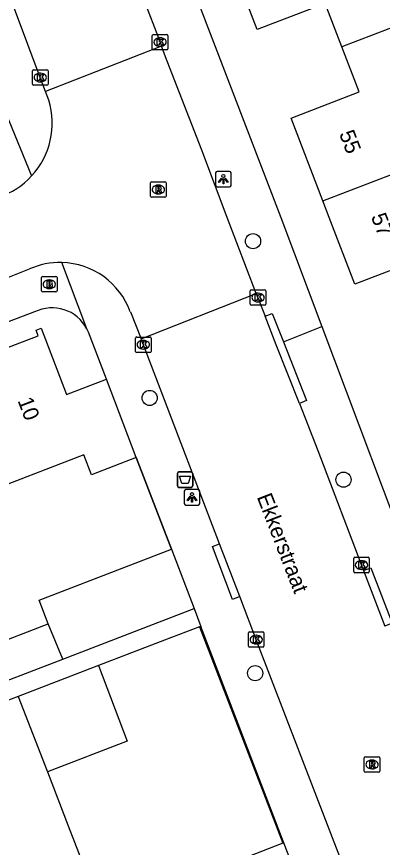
# Model space of a CAD drawing. Extents: x 159265 to 160143, y 383413 to 384319.
# Drawn here: x 159474 to 159497.6, y 383709.4 to 383763 of the extents above; entities that cross this region are included whole.
import ezdxf

# ---------------------------------------------------------------- set-up
doc = ezdxf.new("R2010")
doc.units = 0
for name, color, linetype in [('IMGEO_Afvalbak', 7, 'Continuous'), ('IMGEO_Boom', 7, 'Continuous'), ('IMGEO_Brandkraan', 7, 'Continuous'), ('IMGEO_Kolk', 7, 'Continuous'), ('IMGEO_Lichtpunt', 7, 'Continuous'), ('IMGEO_Muur', 7, 'Continuous'), ('IMGEO_Openbare_ruimte_label', 7, 'Continuous'), ('IMGEO_Pand', 7, 'Continuous'), ('IMGEO_Pand_nummerreeks', 7, 'Continuous'), ('IMGEO_Rijbaan_lokaal_gesloten', 7, 'Continuous'), ('IMGEO_Rijbaan_lokaal_open', 7, 'Continuous'), ('IMGEO_Rioolput', 7, 'Continuous'), ('IMGEO_Voetpad_open', 7, 'Continuous')]:
    doc.layers.add(name, color=color, linetype=linetype)

msp = doc.modelspace()

# ---------------------------------------------------------------- linework, layer by layer
at = {"layer": 'IMGEO_Afvalbak'}
for p, q in [((159484.442, 383733.589), (159485.232, 383733.589)), ((159485.232, 383733.589), (159484.442, 383733.589)), ((159484.342, 383732.689), (159484.342, 383733.489)), ((159484.342, 383733.489), (159484.342, 383732.689)), ((159485.332, 383733.489), (159485.332, 383732.689)), ((159485.332, 383732.689), (159485.332, 383733.489)), ((159485.232, 383732.589), (159484.442, 383732.589)), ((159484.442, 383732.589), (159485.232, 383732.589))]:
    msp.add_line(p, q, dxfattribs=at)
msp.add_lwpolyline([(159484.485, 383733.303), (159485.189, 383733.303), (159485.04, 383732.833), (159484.634, 383732.833), (159484.485, 383733.303)], dxfattribs=at)
for centre, start, end in [((159484.442, 383733.489), 90, 180), ((159484.442, 383733.489), 90, 180), ((159485.232, 383733.489), 0, 90), ((159485.232, 383733.489), 360, 90), ((159484.442, 383732.689), 180, 270), ((159484.442, 383732.689), 180, 270), ((159485.232, 383732.689), 270, 0), ((159485.232, 383732.689), 270, 0)]:
    msp.add_arc(centre, 0.1, start, end, dxfattribs=at)
at = {"layer": 'IMGEO_Boom'}
for centre in [(159489.216, 383748.468), (159482.553, 383738.358), (159495.05, 383733.087), (159489.356, 383720.608)]:
    msp.add_circle(centre, 0.489, dxfattribs=at)
at = {"layer": 'IMGEO_Brandkraan'}
for p, q in [((159475.58, 383745.266), (159475.58, 383746.118)), ((159475.655, 383746.192), (159476.507, 383746.192)), ((159476.068, 383745.972), (159476.093, 383745.972)), ((159476.581, 383746.118), (159476.581, 383745.266)), ((159476.091, 383745.412), (159476.066, 383745.412)), ((159476.507, 383745.192), (159475.655, 383745.192))]:
    msp.add_line(p, q, dxfattribs=at)
for points in [[(159475.58, 383745.266), (159475.58, 383746.118)], [(159475.655, 383746.192), (159476.507, 383746.192)], [(159475.928, 383745.892), (159475.928, 383745.492), (159476.141, 383745.492)], [(159476.159, 383745.892), (159475.928, 383745.892)], [(159476.581, 383746.118), (159476.581, 383745.266)], [(159476.107, 383745.811), (159476.053, 383745.811), (159476.053, 383745.735)], [(159476.053, 383745.735), (159476.106, 383745.735)], [(159476.115, 383745.659), (159476.053, 383745.659), (159476.053, 383745.578)], [(159476.053, 383745.578), (159476.115, 383745.578)], [(159476.507, 383745.192), (159475.655, 383745.192)]]:
    msp.add_lwpolyline(points, dxfattribs=at)
for centre, radius, start, end in [((159475.657, 383746.116), 0.0765, 91.552, 178.448), ((159475.657, 383746.116), 0.0765, 91.552, 178.448), ((159476.163, 383745.747), 0.145, 59.4692, 91.5367), ((159476.188, 383745.794), 0.0922, 285.5137, 58.1501), ((159476.505, 383746.116), 0.0765, 1.552, 88.448), ((159476.505, 383746.116), 0.0765, 1.552, 88.448), ((159476.108, 383745.773), 0.0379, 267.8285, 90.9355), ((159476.116, 383745.618), 0.0404, 269.8759, 90.5077), ((159476.147, 383745.743), 0.251, 268.6676, 293.5347), ((159476.193, 383745.602), 0.105, 301.3115, 78.989), ((159475.657, 383745.268), 0.0765, 181.552, 268.448), ((159475.657, 383745.268), 0.0765, 181.552, 268.448), ((159476.505, 383745.268), 0.0765, 271.552, 358.448), ((159476.505, 383745.268), 0.0765, 271.552, 358.448)]:
    msp.add_arc(centre, radius, start, end, dxfattribs=at)
for centre, major_axis, ratio, start_param, end_param in [((159476.067, 383745.692), (-0.387, 0.002), 0.722429, 4.712389, 7.853982), ((159476.092, 383745.692), (-0.39, 0.002), 0.717154, 1.570796, 4.712389)]:
    msp.add_ellipse(centre, major_axis=major_axis, ratio=ratio, start_param=start_param, end_param=end_param, dxfattribs=at)
at = {"layer": 'IMGEO_Kolk'}
for p, q in [((159482.723, 383760.881), (159482.723, 383761.733)), ((159482.798, 383761.807), (159483.65, 383761.807)), ((159483.211, 383761.587), (159483.236, 383761.587)), ((159483.724, 383761.733), (159483.724, 383760.881)), ((159483.234, 383761.027), (159483.209, 383761.027)), ((159483.65, 383760.807), (159482.798, 383760.807)), ((159474.998, 383758.597), (159474.998, 383759.449)), ((159475.073, 383759.523), (159475.925, 383759.523)), ((159475.486, 383759.303), (159475.511, 383759.303)), ((159475.999, 383759.449), (159475.999, 383758.597)), ((159475.509, 383758.743), (159475.484, 383758.743)), ((159475.925, 383758.523), (159475.073, 383758.523)), ((159489.113, 383745.335), (159489.965, 383745.335)), ((159489.038, 383744.409), (159489.038, 383745.261)), ((159489.526, 383745.115), (159489.551, 383745.115)), ((159490.039, 383745.261), (159490.039, 383744.409)), ((159489.965, 383744.335), (159489.113, 383744.335)), ((159489.549, 383744.555), (159489.524, 383744.555)), ((159481.642, 383741.362), (159481.642, 383742.214)), ((159481.717, 383742.288), (159482.569, 383742.288)), ((159482.13, 383742.068), (159482.155, 383742.068)), ((159482.643, 383742.214), (159482.643, 383741.362)), ((159482.569, 383741.288), (159481.717, 383741.288)), ((159482.153, 383741.508), (159482.128, 383741.508)), ((159495.713, 383727.155), (159495.713, 383728.007)), ((159495.788, 383728.081), (159496.64, 383728.081)), ((159496.201, 383727.861), (159496.226, 383727.861)), ((159496.714, 383728.007), (159496.714, 383727.155)), ((159496.64, 383727.081), (159495.788, 383727.081)), ((159496.224, 383727.301), (159496.199, 383727.301)), ((159488.922, 383722.348), (159488.922, 383723.2)), ((159488.997, 383723.274), (159489.849, 383723.274)), ((159489.41, 383723.054), (159489.435, 383723.054)), ((159489.923, 383723.2), (159489.923, 383722.348)), ((159489.849, 383722.274), (159488.997, 383722.274)), ((159489.433, 383722.494), (159489.408, 383722.494))]:
    msp.add_line(p, q, dxfattribs=at)
for points in [[(159482.723, 383760.881), (159482.723, 383761.733)], [(159482.798, 383761.807), (159483.65, 383761.807)], [(159483.044, 383761.507), (159483.167, 383761.507), (159483.167, 383761.356), (159483.297, 383761.507), (159483.461, 383761.507), (159483.315, 383761.356), (159483.468, 383761.107), (159483.316, 383761.107), (159483.231, 383761.271), (159483.167, 383761.204), (159483.167, 383761.107), (159483.044, 383761.107), (159483.044, 383761.507)], [(159483.724, 383761.733), (159483.724, 383760.881)], [(159483.65, 383760.807), (159482.798, 383760.807)], [(159474.998, 383758.597), (159474.998, 383759.449)], [(159475.073, 383759.523), (159475.925, 383759.523)], [(159475.319, 383759.223), (159475.442, 383759.223), (159475.442, 383759.072), (159475.572, 383759.223), (159475.736, 383759.223), (159475.59, 383759.072), (159475.743, 383758.823), (159475.591, 383758.823), (159475.506, 383758.987), (159475.442, 383758.92), (159475.442, 383758.823), (159475.319, 383758.823), (159475.319, 383759.223)], [(159475.999, 383759.449), (159475.999, 383758.597)], [(159475.925, 383758.523), (159475.073, 383758.523)], [(159489.113, 383745.335), (159489.965, 383745.335)], [(159489.038, 383744.409), (159489.038, 383745.261)], [(159489.359, 383745.035), (159489.482, 383745.035), (159489.482, 383744.884), (159489.612, 383745.035), (159489.776, 383745.035), (159489.63, 383744.884), (159489.783, 383744.635), (159489.631, 383744.635), (159489.546, 383744.799), (159489.482, 383744.732), (159489.482, 383744.635), (159489.359, 383744.635), (159489.359, 383745.035)], [(159490.039, 383745.261), (159490.039, 383744.409)], [(159489.965, 383744.335), (159489.113, 383744.335)], [(159481.642, 383741.362), (159481.642, 383742.214)], [(159481.717, 383742.288), (159482.569, 383742.288)], [(159482.643, 383742.214), (159482.643, 383741.362)], [(159481.963, 383741.988), (159482.086, 383741.988), (159482.086, 383741.837), (159482.216, 383741.988), (159482.38, 383741.988), (159482.234, 383741.837), (159482.387, 383741.588), (159482.235, 383741.588), (159482.15, 383741.752), (159482.086, 383741.685), (159482.086, 383741.588), (159481.963, 383741.588), (159481.963, 383741.988)], [(159482.569, 383741.288), (159481.717, 383741.288)], [(159495.713, 383727.155), (159495.713, 383728.007)], [(159495.788, 383728.081), (159496.64, 383728.081)], [(159496.034, 383727.781), (159496.157, 383727.781), (159496.157, 383727.63), (159496.287, 383727.781), (159496.451, 383727.781), (159496.305, 383727.63), (159496.458, 383727.381), (159496.306, 383727.381), (159496.221, 383727.545), (159496.157, 383727.478), (159496.157, 383727.381), (159496.034, 383727.381), (159496.034, 383727.781)], [(159496.714, 383728.007), (159496.714, 383727.155)], [(159496.64, 383727.081), (159495.788, 383727.081)], [(159488.922, 383722.348), (159488.922, 383723.2)], [(159488.997, 383723.274), (159489.849, 383723.274)], [(159489.243, 383722.974), (159489.366, 383722.974), (159489.366, 383722.823), (159489.496, 383722.974), (159489.66, 383722.974), (159489.514, 383722.823), (159489.667, 383722.574), (159489.515, 383722.574), (159489.43, 383722.738), (159489.366, 383722.671), (159489.366, 383722.574), (159489.243, 383722.574), (159489.243, 383722.974)], [(159489.923, 383723.2), (159489.923, 383722.348)], [(159489.849, 383722.274), (159488.997, 383722.274)]]:
    msp.add_lwpolyline(points, dxfattribs=at)
for centre, start, end in [((159482.8, 383761.731), 91.552, 178.448), ((159482.8, 383761.731), 91.552, 178.448), ((159483.648, 383761.731), 1.552, 88.448), ((159483.648, 383761.731), 1.552, 88.448), ((159482.8, 383760.883), 181.552, 268.448), ((159482.8, 383760.883), 181.552, 268.448), ((159483.648, 383760.883), 271.552, 358.448), ((159483.648, 383760.883), 271.552, 358.448), ((159475.075, 383759.447), 91.552, 178.448), ((159475.075, 383759.447), 91.552, 178.448), ((159475.923, 383759.447), 1.552, 88.448), ((159475.923, 383759.447), 1.552, 88.448), ((159475.075, 383758.599), 181.552, 268.448), ((159475.075, 383758.599), 181.552, 268.448), ((159475.923, 383758.599), 271.552, 358.448), ((159475.923, 383758.599), 271.552, 358.448), ((159489.115, 383745.259), 91.552, 178.448), ((159489.115, 383745.259), 91.552, 178.448), ((159489.963, 383745.259), 1.552, 88.448), ((159489.963, 383745.259), 1.552, 88.448), ((159489.115, 383744.411), 181.552, 268.448), ((159489.115, 383744.411), 181.552, 268.448), ((159489.963, 383744.411), 271.552, 358.448), ((159489.963, 383744.411), 271.552, 358.448), ((159481.719, 383742.212), 91.552, 178.448), ((159481.719, 383742.212), 91.552, 178.448), ((159482.567, 383742.212), 1.552, 88.448), ((159482.567, 383742.212), 1.552, 88.448), ((159481.719, 383741.364), 181.552, 268.448), ((159481.719, 383741.364), 181.552, 268.448), ((159482.567, 383741.364), 271.552, 358.448), ((159482.567, 383741.364), 271.552, 358.448), ((159495.79, 383728.005), 91.552, 178.448), ((159495.79, 383728.005), 91.552, 178.448), ((159496.638, 383728.005), 1.552, 88.448), ((159496.638, 383728.005), 1.552, 88.448), ((159495.79, 383727.157), 181.552, 268.448), ((159495.79, 383727.157), 181.552, 268.448), ((159496.638, 383727.157), 271.552, 358.448), ((159496.638, 383727.157), 271.552, 358.448), ((159488.999, 383723.198), 91.552, 178.448), ((159488.999, 383723.198), 91.552, 178.448), ((159489.847, 383723.198), 1.552, 88.448), ((159489.847, 383723.198), 1.552, 88.448), ((159488.999, 383722.35), 181.552, 268.448), ((159488.999, 383722.35), 181.552, 268.448), ((159489.847, 383722.35), 271.552, 358.448), ((159489.847, 383722.35), 271.552, 358.448)]:
    msp.add_arc(centre, 0.0765, start, end, dxfattribs=at)
for centre, major_axis, ratio, start_param, end_param in [((159483.21, 383761.307), (-0.387, 0.002), 0.722429, 4.712389, 7.853982), ((159483.235, 383761.307), (-0.39, 0.002), 0.717154, 1.570796, 4.712389), ((159475.485, 383759.023), (-0.387, 0.002), 0.722429, 4.712389, 7.853982), ((159475.51, 383759.023), (-0.39, 0.002), 0.717154, 1.570796, 4.712389), ((159489.525, 383744.835), (-0.387, 0.002), 0.722429, 4.712389, 7.853982), ((159489.55, 383744.835), (-0.39, 0.002), 0.717154, 1.570796, 4.712389), ((159482.129, 383741.788), (-0.387, 0.002), 0.722429, 4.712389, 7.853982), ((159482.154, 383741.788), (-0.39, 0.002), 0.717154, 1.570796, 4.712389), ((159496.2, 383727.581), (-0.387, 0.002), 0.722429, 4.712389, 7.853982), ((159496.225, 383727.581), (-0.39, 0.002), 0.717154, 1.570796, 4.712389), ((159489.409, 383722.774), (-0.387, 0.002), 0.722429, 4.712389, 7.853982), ((159489.434, 383722.774), (-0.39, 0.002), 0.717154, 1.570796, 4.712389)]:
    msp.add_ellipse(centre, major_axis=major_axis, ratio=ratio, start_param=start_param, end_param=end_param, dxfattribs=at)
at = {"layer": 'IMGEO_Lichtpunt'}
for p, q in [((159486.806, 383752.873), (159486.806, 383752.066)), ((159486.806, 383752.873), (159486.806, 383752.066)), ((159487.708, 383752.968), (159486.9, 383752.968)), ((159487.708, 383752.968), (159486.9, 383752.968)), ((159487.802, 383752.066), (159487.802, 383752.873)), ((159487.802, 383752.066), (159487.802, 383752.873)), ((159486.9, 383751.972), (159487.708, 383751.972)), ((159486.9, 383751.972), (159487.708, 383751.972)), ((159485.686, 383732.447), (159484.878, 383732.447)), ((159485.686, 383732.447), (159484.878, 383732.447)), ((159484.784, 383732.352), (159484.784, 383731.545)), ((159484.784, 383732.352), (159484.784, 383731.545)), ((159485.78, 383731.545), (159485.78, 383732.352)), ((159485.78, 383731.545), (159485.78, 383732.352)), ((159484.878, 383731.451), (159485.686, 383731.451)), ((159484.878, 383731.451), (159485.686, 383731.451))]:
    msp.add_line(p, q, dxfattribs=at)
for points in [[(159487.18, 383752.537), (159487.219, 383752.509), (159487.031, 383752.247), (159486.993, 383752.274), (159487.18, 383752.537)], [(159487.282, 383752.489), (159487.329, 383752.489), (159487.329, 383752.167), (159487.282, 383752.167), (159487.282, 383752.489)], [(159487.392, 383752.509), (159487.43, 383752.536), (159487.617, 383752.274), (159487.578, 383752.246), (159487.392, 383752.509)], [(159485.158, 383732.016), (159485.197, 383731.988), (159485.009, 383731.726), (159484.971, 383731.753), (159485.158, 383732.016)], [(159485.26, 383731.968), (159485.307, 383731.968), (159485.307, 383731.646), (159485.26, 383731.646), (159485.26, 383731.968)], [(159485.37, 383731.988), (159485.408, 383732.015), (159485.595, 383731.753), (159485.556, 383731.725), (159485.37, 383731.988)]]:
    msp.add_lwpolyline(points, dxfattribs=at)
for centre in [(159487.305, 383752.671), (159485.283, 383732.15)]:
    msp.add_circle(centre, 0.0994, dxfattribs=at)
for centre, start, end in [((159486.9, 383752.873), 90, 180), ((159486.9, 383752.873), 90, 180), ((159487.708, 383752.873), 0, 90), ((159487.708, 383752.873), 0, 90), ((159486.9, 383752.066), 180, 270), ((159486.9, 383752.066), 180, 270), ((159487.708, 383752.066), 270, 0), ((159487.708, 383752.066), 270, 360), ((159484.878, 383732.352), 90, 180), ((159484.878, 383732.352), 90, 180), ((159485.686, 383732.352), 0, 90), ((159485.686, 383732.352), 0, 90), ((159484.878, 383731.545), 180, 270), ((159484.878, 383731.545), 180, 270), ((159485.686, 383731.545), 270, 0), ((159485.686, 383731.545), 270, 360)]:
    msp.add_arc(centre, 0.0946, start, end, dxfattribs=at)
at = {"layer": 'IMGEO_Muur'}
msp.add_lwpolyline([(159481.692, 383734.52), (159483.955, 383728.599)], dxfattribs=at)
at = {"layer": 'IMGEO_Pand'}
for points in [[(159494.951, 383761.005), (159493.876, 383763.807), (159489.475, 383762.119), (159487.395, 383767.541)], [(159500.424, 383763.095), (159500, 383762.933), (159494.951, 383761.005)], [(159493.714, 383751.078), (159491.668, 383756.411), (159496.067, 383758.098), (159494.951, 383761.005)], [(159493.714, 383751.078), (159500, 383753.487), (159502.011, 383754.257)], [(159502.855, 383745.139), (159501.768, 383748.001), (159500, 383747.318), (159495.782, 383745.687), (159494.127, 383750), (159493.714, 383751.078)], [(159469.621, 383740.58), (159469.817, 383740.655), (159469.956, 383740.291), (159475.364, 383742.37), (159475.224, 383742.733), (159475.556, 383742.861), (159477.2, 383738.588), (159479.759, 383739.576)], [(159481.692, 383734.52), (159479.759, 383739.576)], [(159481.692, 383734.52), (159478.794, 383733.402), (159478.299, 383734.69), (159472.711, 383732.544)], [(159476.006, 383723.798), (159475.423, 383725.318), (159481.33, 383727.59), (159483.955, 383728.599)], [(159483.955, 383728.599), (159485.418, 383724.77)], [(159476.954, 383721.516), (159482.801, 383723.764), (159485.418, 383724.77)], [(159472.929, 383720.123), (159472.095, 383722.294), (159476.006, 383723.798)], [(159476.954, 383721.516), (159476.006, 383723.798)], [(159485.763, 383723.591), (159483.511, 383722.728), (159479.244, 383721.092)], [(159485.763, 383723.591), (159491.137, 383709.634), (159488.886, 383708.768), (159489.964, 383705.968), (159485.036, 383704.069), (159484.913, 383704.379), (159485.114, 383704.464), (159484.759, 383705.406), (159482.797, 383704.653), (159482.376, 383705.767), (159479.829, 383704.783), (159479.649, 383704.714)], [(159472.929, 383720.123), (159472.981, 383719.988), (159476.954, 383721.516)], [(159479.244, 383721.092), (159481.112, 383716.217), (159475.962, 383714.243)], [(159474.079, 383719.112), (159470, 383717.549)], [(159474.079, 383719.112), (159475.962, 383714.243)], [(159475.962, 383714.243), (159477.308, 383710.765), (159479.649, 383704.714)]]:
    msp.add_lwpolyline(points, dxfattribs=at)
at = {"layer": 'IMGEO_Rijbaan_lokaal_gesloten'}
for points in [[(159475.831, 383758.13), (159475.5, 383759.023), (159472.225, 383767.721), (159469.529, 383774.749)], [(159479.585, 383770.783), (159483.224, 383761.306), (159483.308, 383761.046)], [(159489.424, 383745.092), (159489.992, 383743.627)], [(159492.205, 383738.007), (159490.718, 383741.784), (159489.992, 383743.627)], [(159487.06, 383728.953), (159482.959, 383739.704), (159482.013, 383742.165)], [(159492.205, 383738.007), (159493.397, 383734.979), (159496.348, 383727.229)], [(159488.361, 383725.542), (159487.06, 383728.953)], [(159496.348, 383727.229), (159497.711, 383723.646)], [(159496.217, 383705.045), (159495.821, 383706.144), (159489.512, 383722.543), (159488.361, 383725.542)]]:
    msp.add_lwpolyline(points, dxfattribs=at)
at = {"layer": 'IMGEO_Rijbaan_lokaal_open'}
for points in [[(159483.308, 383761.046), (159475.831, 383758.13)], [(159489.424, 383745.092), (159487.543, 383750), (159485.92, 383754.33), (159483.68, 383760.076), (159483.308, 383761.046)], [(159476.042, 383757.553), (159475.831, 383758.13)], [(159473.29, 383746.085), (159474.804, 383746.675)], [(159482.013, 383742.165), (159489.424, 383745.092)], [(159481.306, 383743.909), (159482.013, 383742.165)]]:
    msp.add_lwpolyline(points, dxfattribs=at)
for centre, radius, start, end in [((159471.279, 383756.063), 4.99, 317.1884, 17.3665), ((159471.28, 383756.055), 4.984, 288.3378, 317.2544), ((159476.758, 383742.279), 4.811, 88.4427, 113.9657), ((159476.764, 383742.257), 4.833, 19.992, 88.5214)]:
    msp.add_arc(centre, radius, start, end, dxfattribs=at)
at = {"layer": 'IMGEO_Rioolput'}
for p, q in [((159482.686, 383752.301), (159483.538, 383752.301)), ((159482.611, 383751.375), (159482.611, 383752.227)), ((159483.099, 383752.081), (159483.124, 383752.081)), ((159483.612, 383752.227), (159483.612, 383751.375)), ((159483.538, 383751.301), (159482.686, 383751.301)), ((159483.122, 383751.521), (159483.097, 383751.521)), ((159496.389, 383714.293), (159496.389, 383715.145)), ((159496.464, 383715.219), (159497.316, 383715.219)), ((159496.877, 383714.999), (159496.902, 383714.999)), ((159497.39, 383715.145), (159497.39, 383714.293)), ((159497.316, 383714.219), (159496.464, 383714.219)), ((159496.9, 383714.439), (159496.875, 383714.439))]:
    msp.add_line(p, q, dxfattribs=at)
for points in [[(159482.686, 383752.301), (159483.538, 383752.301)], [(159482.611, 383751.375), (159482.611, 383752.227)], [(159483.2, 383751.999), (159482.948, 383752.001), (159482.948, 383751.601)], [(159482.948, 383751.601), (159483.072, 383751.601), (159483.072, 383751.763), (159483.083, 383751.763)], [(159483.126, 383751.92), (159483.072, 383751.92), (159483.072, 383751.839)], [(159483.072, 383751.839), (159483.124, 383751.839)], [(159483.13, 383751.734), (159483.201, 383751.601), (159483.341, 383751.601), (159483.276, 383751.727)], [(159483.612, 383752.227), (159483.612, 383751.375)], [(159483.538, 383751.301), (159482.686, 383751.301)], [(159496.389, 383714.293), (159496.389, 383715.145)], [(159496.464, 383715.219), (159497.316, 383715.219)], [(159496.978, 383714.917), (159496.726, 383714.919), (159496.726, 383714.519)], [(159496.904, 383714.838), (159496.85, 383714.838), (159496.85, 383714.757)], [(159496.85, 383714.757), (159496.902, 383714.757)], [(159497.39, 383715.145), (159497.39, 383714.293)], [(159497.316, 383714.219), (159496.464, 383714.219)], [(159496.726, 383714.519), (159496.85, 383714.519), (159496.85, 383714.681), (159496.861, 383714.681)], [(159496.908, 383714.652), (159496.979, 383714.519), (159497.119, 383714.519), (159497.054, 383714.645)]]:
    msp.add_lwpolyline(points, dxfattribs=at)
for centre, radius, start, end in [((159482.688, 383752.225), 0.0765, 91.552, 178.448), ((159482.688, 383752.225), 0.0765, 91.552, 178.448), ((159483.536, 383752.225), 0.0765, 1.552, 88.448), ((159483.536, 383752.225), 0.0765, 1.552, 88.448), ((159483.082, 383751.71), 0.0533, 26.0293, 88.6989), ((159483.108, 383752.028), 0.19, 274.7715, 282.9687), ((159483.132, 383751.824), 0.0964, 77.0061, 93.1865), ((159483.146, 383751.881), 0.0378, 276.6634, 79.6772), ((159483.199, 383751.889), 0.109, 350.3612, 89.416), ((159483.197, 383751.889), 0.112, 277.5842, 350.9817), ((159483.181, 383751.674), 0.108, 29.5134, 73.7905), ((159482.688, 383751.377), 0.0765, 181.552, 268.448), ((159482.688, 383751.377), 0.0765, 181.552, 268.448), ((159483.536, 383751.377), 0.0765, 271.552, 358.448), ((159483.536, 383751.377), 0.0765, 271.552, 358.448), ((159496.466, 383715.143), 0.0765, 91.552, 178.448), ((159496.466, 383715.143), 0.0765, 91.552, 178.448), ((159496.886, 383714.946), 0.19, 274.7715, 282.9687), ((159496.91, 383714.742), 0.0964, 77.0061, 93.1865), ((159496.924, 383714.799), 0.0378, 276.6634, 79.6772), ((159496.977, 383714.807), 0.109, 350.3612, 89.416), ((159496.975, 383714.807), 0.112, 277.5842, 350.9817), ((159497.314, 383715.143), 0.0765, 1.552, 88.448), ((159497.314, 383715.143), 0.0765, 1.552, 88.448), ((159496.466, 383714.295), 0.0765, 181.552, 268.448), ((159496.466, 383714.295), 0.0765, 181.552, 268.448), ((159496.86, 383714.628), 0.0533, 26.0293, 88.6989), ((159496.959, 383714.592), 0.108, 29.5134, 73.7905), ((159497.314, 383714.295), 0.0765, 271.552, 358.448), ((159497.314, 383714.295), 0.0765, 271.552, 358.448)]:
    msp.add_arc(centre, radius, start, end, dxfattribs=at)
for centre, major_axis, ratio, start_param, end_param in [((159483.098, 383751.801), (-0.387, 0.002), 0.722429, 4.712389, 7.853982), ((159483.123, 383751.801), (-0.39, 0.002), 0.717154, 1.570796, 4.712389), ((159496.876, 383714.719), (-0.387, 0.002), 0.722429, 4.712389, 7.853982), ((159496.901, 383714.719), (-0.39, 0.002), 0.717154, 1.570796, 4.712389)]:
    msp.add_ellipse(centre, major_axis=major_axis, ratio=ratio, start_param=start_param, end_param=end_param, dxfattribs=at)
at = {"layer": 'IMGEO_Voetpad_open'}
for points in [[(159458.43, 383834.836), (159491.014, 383750), (159493.662, 383742.956)], [(159472.73, 383758.03), (159474.94, 383752.672)], [(159478.507, 383742.809), (159476.889, 383747.088)], [(159475.133, 383743.901), (159411.208, 383719.553), (159411.043, 383719.484)], [(159489.992, 383743.627), (159490.457, 383743.81), (159491.182, 383741.969)], [(159479.759, 383739.576), (159478.603, 383742.601), (159478.507, 383742.809)], [(159491.182, 383741.969), (159493.662, 383742.956)], [(159493.662, 383742.956), (159500, 383726.102), (159501.344, 383722.528)], [(159491.182, 383741.969), (159492.67, 383738.19), (159492.205, 383738.007)], [(159483.955, 383728.599), (159481.692, 383734.52)], [(159488.361, 383725.542), (159487.894, 383725.364), (159486.593, 383728.775), (159487.06, 383728.953)], [(159496.348, 383727.229), (159496.815, 383727.407), (159498.178, 383723.824), (159497.711, 383723.646)], [(159485.418, 383724.77), (159485.853, 383723.626)], [(159485.853, 383723.626), (159485.763, 383723.591)], [(159493.36, 383704.052), (159485.859, 383723.61), (159485.853, 383723.626)], [(159479.244, 383721.092), (159474.079, 383719.112)]]:
    msp.add_lwpolyline(points, dxfattribs=at)
msp.add_arc((159476.27, 383741.654), 2.518, 27.3001, 116.8314, dxfattribs=at)

# ---------------------------------------------------------------- texts
at = {"layer": 'IMGEO_Openbare_ruimte_label'}
msp.add_text('Ekkerstraat', height=1, rotation=291.2268, dxfattribs=at).set_placement((159489.447, 383731.977))
at = {"layer": 'IMGEO_Pand_nummerreeks'}
for s, rotation, p in [('55', 290.9872, (159494.754, 383755.405)), ('57', 290.9869, (159496.806, 383750.058)), ('10', 291.0438, (159474.023, 383738.193))]:
    msp.add_text(s, height=1, rotation=rotation, dxfattribs=at).set_placement(p)

doc.saveas('drawing.dxf')
